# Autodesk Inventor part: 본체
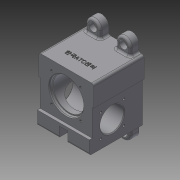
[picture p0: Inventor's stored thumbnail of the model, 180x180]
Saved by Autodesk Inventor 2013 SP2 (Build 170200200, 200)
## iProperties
Created: 2024-11
Part Number: 본체
Material: Generic
Document SubType Name: Modeling
Designer: a
Density: 1 g/cm^3
Author: a
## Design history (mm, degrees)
sketch "스케치1"
  geometry: L1 (-38, -42.5)-(38, -42.5); L2 (38, -42.5)-(38, 42.5); L3 (38, 42.5)-(-38, 42.5); L4 (-38, 42.5)-(-38, -42.5); L5 (-38, -42.5)-(38, 42.5); L6 (38, -42.5)-(-38, 42.5); 1 further point
  constraints: 12 end point, 2 midpoint, 2 parallel, 1 horizontal, 1 perpendicular
  dimensions: "d0" = 76 distance of L2.end L3.end; "d2" = 85 distance of L1.end L2.end
extrude "돌출1" new body sketch "스케치1" stored distance "d3" = 74; taper "d4" = 0 deg
sketch "스케치3"
  geometry: L1 (-38, 13.5)-(-36, 13.5); L2 (-36, 13.5)-(-36, -42.5); L3 (-36, -42.5)-(-38, -42.5); L4 (-38, -42.5)-(-38, 13.5); L5 (-38, 13.5)-(-36, -42.5); L6 (-36, 13.5)-(-38, -42.5); L7 (36, 13.5)-(38, 13.5); L8 (38, 13.5)-(38, -42.5); L9 (38, -42.5)-(36, -42.5); L10 (36, -42.5)-(36, 13.5); L11 (36, 13.5)-(38, -42.5); L12 (38, 13.5)-(36, -42.5); 3 further points
  constraints: 24 end point, 4 midpoint, 4 parallel, 2 horizontal, 2 perpendicular
  dimensions: "d10" = 2 distance of L1.start L1.end; "d12" = 2 distance of L7.start L7.end; "d13" = 56 distance of L1.end L2.end; "d14" = 56 distance of L9.end L7.start
extrude "돌출3" cut sketch "스케치3" stored distance "d15" = 74; taper "d16" = 0 deg
sketch "스케치5"
  geometry: L1 (-42.5, 37)-(42.5, 37) reference; L2 (42.5, 37)-(42.5, -37) reference; L3 (42.5, -37)-(-42.5, -37) reference; L4 (-42.5, -37)-(-42.5, 37) reference; L5 (42.5, 37)-(-23.5, 37); L6 (-23.5, 37)-(-23.5, 33); L7 (-23.5, 33)-(42.5, 33); L8 (42.5, 33)-(42.5, 37); L9 (42.5, 37)-(-23.5, 33); L10 (-23.5, 37)-(42.5, 33); 2 further points
  constraints: 12 end point, 2 midpoint, 2 parallel, 1 horizontal, 1 perpendicular
  dimensions: "d17" = 4 distance of L5.end L6.end; "d19" = 66 distance of L6.end L7.end
extrude "돌출4" cut sketch "스케치5" stored distance "d20" = 76; taper "d21" = 0 deg
sketch "스케치6"
  geometry: L1 (-36, -42.5)-(36, -42.5) reference; L2 (-6, -27.5)-(6, -27.5); L3 (6, -27.5)-(6, -42.5); L4 (6, -42.5)-(-6, -42.5); L5 (-6, -42.5)-(-6, -27.5); L6 (-6, -27.5)-(6, -42.5); L7 (6, -27.5)-(-6, -42.5); 4 further points
  constraints: 12 end point, 5 midpoint, 2 parallel, 1 horizontal, 1 perpendicular, 1 vertical alignment
  dimensions: "d22" = 12 distance of L2.start L2.end; "d24" = 15 distance of L2.end L3.end
extrude "돌출5" cut sketch "스케치6" stored distance "d25" = 76; taper "d26" = 0 deg
sketch "스케치7"
  geometry: L1 (-23.5, 33)-(42.5, 33) reference; L2 (42.5, 33)-(42.5, -37) reference; L3 (42.5, -37)-(-27.5, -37) reference; L4 (-27.5, -37)-(-27.5, 37) reference; L5 (-27.5, 37)-(-23.5, 37) reference; L6 (-23.5, 37)-(-23.5, 33) reference; L7 (9.5, 33)-(9.5, -33); L8 (9.5, -33)-(21.5, -33); L9 (24.5, -30)-(24.5, -30); L10 (24.5, -30)-(26.4, -30); L11 (27, -29.4)-(27, -19); L12 (27, -19)-(28.5, -19); L13 (31.5, -16)-(31.5, 29); L14 (31.5, 29)-(33, 29); L15 (33, 29)-(33, 33); L16 (33, 33)-(9.5, 33); A1 r 0.6 centre (26.4, -29.4) between (26.4, -30) and (27, -29.4); A2 r 3 centre (21.5, -30) between (21.5, -33) and (24.5, -30); A3 r 3 centre (28.5, -16) between (28.5, -19) and (31.5, -16); 4 further points
  constraints: 20 end point, 9 parallel, 6 point on circle, 6 point on line, 6 tangent, 3 centre point, 1 equal radius, 1 midpoint, 1 perpendicular
  dimensions: "d35" = 33 distance from line of L7.start L2; "d36" = 47 diameter of L15 L7; "d37" = 44 diameter of L13 L7; "d38" = 35 diameter of L11 L7; "d39" = 30 diameter of L9 L7; "d40" = 4 distance of L14.end L15.end; "d41" = 11 distance of point (27, -30) L11.end; "d42" = 3 distance of point (24.5, -33) L9.end; "d43" = 66 distance of L7.start L7.end; "d125" = 0.6 radius of A1; "d126" = 3 radius of A2
revolve "회전1" sketch "스케치7" stored, may be unused: angle "d44" = 90 deg
sketch "스케치9"
  geometry: L1 (0, -29)-(0, 0) reference; L2 (9.5, -33)-(66.5, -33); L3 (38, -4.5)-(38, -61.5); L4 (38, -33)-(17.847, -12.847); C1 r 23.5 at (38, -33) reference; A1 r 28.5 centre (38, -33) between (9.5, -33) and (66.5, -33); 2 further points
  constraints: 6 end point, 5 point on circle, 2 coincident, 2 perpendicular, 1 centre point
  dimensions: "d47" = 57 diameter of A1; "d50" = 45 deg angle of L3 L4
hole "구멍1" sketch "스케치9" at (17.847, -12.847) diameter "d52" = 3.242; stored, may be unused: countersink angle "d56" = 90 deg, drill point angle "d58" = 118 deg; dims "d53" = 8, "d54" = 4, "d55" = 2, "d57" = 10
sketch "스케치11"
  geometry: L1 (-27.5, -37)-(-27.5, 37) reference; L2 (-27.5, 37)-(-23.5, 37) reference; L3 (-23.5, 37)-(-23.5, 33) reference; L4 (-23.5, 33)-(-14, 33) reference; L5 (-14, 33)-(-14, 29) reference; L6 (-14, 29)-(-12.5, 29) reference; L7 (-12.5, 29)-(-12.5, -16) reference; L8 (-9.5, -19)-(-8, -19) reference; L9 (-8, -19)-(-8, -29.4) reference; L10 (-7.4, -30)-(-5.5, -30) reference; L11 (24.5, -30)-(26.4, -30) reference; L12 (27, -29.4)-(27, -19) reference; L13 (27, -19)-(28.5, -19) reference; L14 (31.5, -16)-(31.5, 29) reference; L15 (31.5, 29)-(33, 29) reference; L16 (33, 29)-(33, 33) reference; L17 (33, 33)-(42.5, 33) reference; L18 (42.5, 33)-(42.5, -37) reference; L19 (42.5, -37)-(-27.5, -37) reference; L20 (-14, 33)-(33, 33) reference; L21 (9.5, 33)-(9.5, -37); L22 (-2.5, -33)-(21.5, -33) reference; C1 r 16.5 at (-14.5, 5); A1 r 3 centre (-9.5, -16) between (-12.5, -16) and (-9.5, -19) reference; A2 r 0.6 centre (-7.4, -29.4) between (-8, -29.4) and (-7.4, -30) reference; A3 r 3 centre (-2.5, -30) between (-5.5, -30) and (-2.5, -33) reference; A4 r 3 centre (21.5, -30) between (21.5, -33) and (24.5, -30) reference; A5 r 0.6 centre (26.4, -29.4) between (26.4, -30) and (27, -29.4) reference; A6 r 3 centre (28.5, -16) between (28.5, -19) and (31.5, -16) reference; 1 further point
  constraints: 2 end point, 1 centre point, 1 midpoint, 1 perpendicular, 1 point on line
  dimensions: "d62" = 33 diameter of C1; "d63" = 42 distance from line of C1.centre L19; "d65" = 24 distance from line of C1.centre L21
extrude "돌출6" cut sketch "스케치11" stored distance "d66" = 76; taper "d67" = 0 deg
sketch "스케치12"
  geometry: L1 (74, 19)-(70, 19) reference; L2 (25.5, 28)-(58.5, 28); L3 (42, 44.5)-(42, 11.5); L4 (42, 28)-(58, 12); A1 r 16.5 centre (42, 28) between (25.5, 28) and (58.5, 28) reference; 1 further point
  constraints: 6 end point, 4 point on circle, 1 parallel, 1 perpendicular
  dimensions: "d69" = 16 distance from line of L4.end L2; "d70" = 16 horizontal distance of L4.end L4.start; "d71" = 45 deg angle of L2 L4
hole "구멍2" sketch "스케치12" at (58, 12) diameter "d72" = 3.242; stored, may be unused: countersink angle "d76" = 90 deg, drill point angle "d78" = 118 deg; dims "d73" = 8, "d74" = 4, "d75" = 2, "d77" = 10
sketch "스케치13"
  geometry: L1 (38, 42.5)-(-38, 42.5) reference; L2 (-11, 52.5)-(-31, 52.5); L3 (-31, 52.5)-(-31, 42.5); L4 (-31, 42.5)-(-11, 42.5); L5 (-11, 42.5)-(-11, 52.5); L6 (-11, 52.5)-(-31, 42.5); L7 (-31, 52.5)-(-11, 42.5); A1 r 10 centre (-21, 52.5) between (-11, 52.5) and (-31, 52.5); 4 further points
  constraints: 12 end point, 4 midpoint, 2 parallel, 2 point on circle, 1 centre point, 1 coincident, 1 horizontal, 1 perpendicular, 1 point on line
  dimensions: "d82" = 21 horizontal distance of point (0, 0) point (-21, 42.5); "d83" = 20 distance of L3.end L4.end; "d84" = 10 distance between parallel lines of L4 L2
extrude "돌출7" join sketch "스케치13" distance "d85" = 12; taper "d86" = 0 deg
sketch "스케치14"
  geometry: A1 r 10 centre (0, 0) between (10, 0) and (-10, 0) reference; 2 further points
  constraints: 1 coincident
hole "구멍3" sketch "스케치14" at (0, 0) diameter "d87" = 6.6; stored, may be unused: countersink angle "d91" = 90 deg, drill point angle "d93" = 0 deg; dims "d88" = 8, "d89" = 11, "d90" = 6.6, "d92" = 10
chamfer "모따기1" distance "d96" = 1; stored, may be unused: second distance "d97" = 2, angle "d98" = 45 deg
chamfer "모따기2" distance "d99" = 1; stored, may be unused: second distance "d100" = 2, angle "d101" = 45 deg
fillet "모깎기1" dims "d102" = 3
fillet "모깎기2" dims "d103" = 3
fillet "모깎기3" dims "d104" = 3
fillet "모깎기4" dims "d105" = 3
fillet "모깎기5" dims "d106" = 3
chamfer "모따기3" distance "d107" = 1; stored, may be unused: second distance "d108" = 2, angle "d109" = 45 deg
fillet "모깎기6" dims "d110" = 3
sketch "스케치17"
  geometry: L1 (0, 0)-(12, 0) reference; L2 (-30, 0)-(0, 0) reference; L3 (0, 0)-(12, 0) reference; L4 (12, 0)-(42, 0) reference; L5 (42, 0)-(42, -20.285) reference; L6 (41, -21.839)-(12, -21.839) reference; L7 (12, -21.839)-(0, -21.839) reference; L8 (0, -21.839)-(-29, -21.839) reference; L9 (-30, -20.285)-(-30, 0) reference; L10 (0, 0)-(0, -21.839) reference; L11 (12, -21.839)-(12, 0) reference; L12 (12, -74)-(12, -42.161) reference; L13 (0, -42.161)-(12, -42.161) reference; L14 (-29, -42.161)-(0, -42.161) reference; L15 (-30, -74)-(-30, -43.715) reference; L16 (0, -74)-(-30, -74) reference; L17 (0, -42.161)-(0, -74) reference; L18 (12, -74)-(0, -74) reference; L19 (42, -74)-(12, -74) reference; L20 (42, -43.715)-(42, -74) reference; L21 (12, -42.161)-(41, -42.161) reference; 3 further points
  constraints: 2 vertical alignment, 4 other
  dimensions: "d111" = 12 distance from line of point (6, -12) L1; "d112" = 40 distance of point (6, -52) point (6, -12)
hole "구멍4" sketch "스케치17" at (6, -12), (6, -52) diameter "d113" = 3.242; stored, may be unused: countersink angle "d117" = 90 deg, drill point angle "d119" = 118 deg; dims "d114" = 8, "d115" = 11, "d116" = 6.6, "d118" = 10
node "작업 평면1"
sketch "스케치18"
  geometry: L1 (20.74, 8.113)-(-20.74, 8.113); L2 (-20.74, 8.113)-(-20.74, 17.887); L3 (-20.74, 17.887)-(20.74, 17.887); L4 (20.74, 17.887)-(20.74, 8.113); L5 (20.74, 13)-(-20.74, 13); L6 (0, 8.113)-(0, 17.887); L7 (35, 33)-(-35, 33) reference; 2 further points
  constraints: 5 midpoint, 4 end point, 1 vertical alignment, 2 other
  dimensions: "d121" = 20 distance from line of L5.end L7
feature "엠보싱1" sketch "스케치18" dims "d0" = 76, "d2" = 85, "d122" = 0.5, "d123" = 0
node "솔리드1"
pattern_circular "원형 패턴1" dims angle "d60" = 360 deg
pattern_circular "원형 패턴2" dims angle "d80" = 360 deg
mirror "대칭1"
mirror "대칭2"
mirror "대칭3"
mirror "대칭4"
mirror "대칭5"
node "절단 모서리 투영2"
node "절단 모서리 투영3"
node "절단 모서리 투영4"
node "절단 모서리 투영7"
other parameters: "d120" = 50.5
